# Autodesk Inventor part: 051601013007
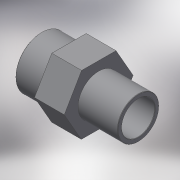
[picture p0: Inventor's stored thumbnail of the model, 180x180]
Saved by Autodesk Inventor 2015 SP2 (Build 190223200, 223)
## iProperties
Created: 2017-10
Part Number: 051601013007
Material: Generic
Description: PLASSON THR. REDUCING NIPPLE 1.1/4"-3/4" PVC
Document SubType Name: Modeling
Designer: KIM
Density: 1 g/cm^3
Appearance: Default
Author: KIM
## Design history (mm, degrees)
derived "051601.ipt"
feature "Solid1::051601.ipt"
tag "TaggingFeature1"
body "Solid1"
other parameters: "d0" = 57, "d13" = 0, "d14" = 0.26441, "d17" = 19, "d18" = 26.4, "d19" = 41.91, "d21" = 26.441, "d23" = 33.528, "d24" = 21.1528, "d25" = 22, "d26" = -19, "R_1" = 26.441, "lt_1" = 19, "lt_" = 22, "H_" = 57, "R_" = 41.91
